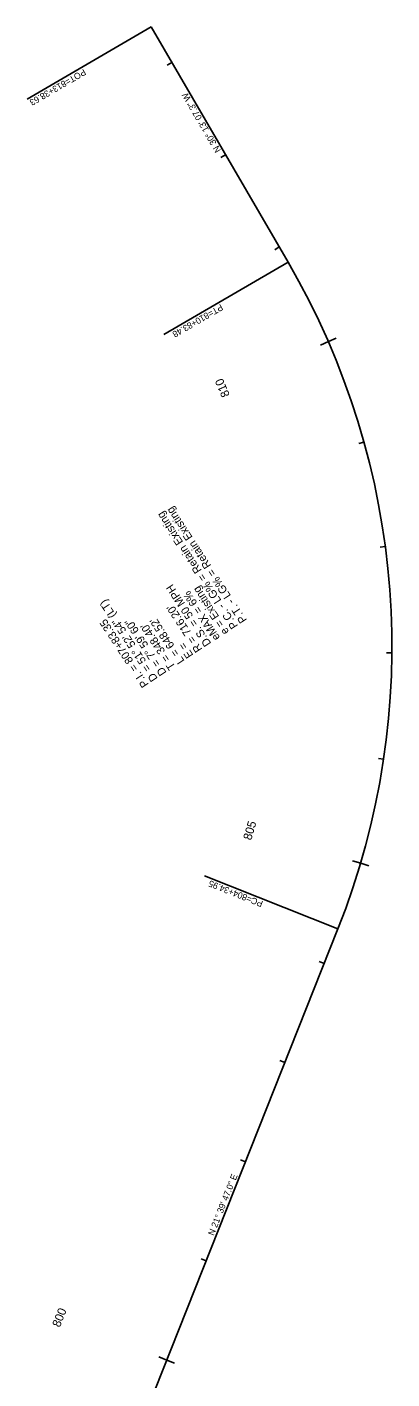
# Model space of a CAD drawing. Extents: x 1551641 to 1624343, y 1119533 to 1136600.
# Drawn here: x 1552292 to 1552634, y 1135333 to 1136600 of the extents above; entities that cross this region are included whole.
import ezdxf

# ---------------------------------------------------------------- set-up
doc = ezdxf.new("R2010")
doc.units = 0
for name, color, linetype in [('RD_HC_Cl', 7, 'Continuous'), ('RD_HC_Data', 7, 'Continuous'), ('RD_HC_Data_Tic', 7, 'Continuous'), ('RD_HC_TX_Sta50', 7, 'Continuous')]:
    doc.layers.add(name, color=color, linetype=linetype)

msp = doc.modelspace()

# ---------------------------------------------------------------- linework, layer by layer
at = {"layer": 'RD_HC_Cl'}
for p, q in [((1552536.7, 1136379.5), (1552408.3, 1136600)), ((1552389.3, 1135265.7), (1552583.4, 1135754.6))]:
    msp.add_line(p, q, dxfattribs=at)
msp.add_arc((1551917.8, 1136019), 716.2, 338.3369, 30.2187, dxfattribs=at)
at = {"layer": 'RD_HC_Data'}
for p, q in [((1552408.3, 1136600), (1552291.9, 1136532.2)), ((1552536.7, 1136379.5), (1552420.3, 1136311.7)), ((1552583.4, 1135754.6), (1552458.3, 1135804.4))]:
    msp.add_line(p, q, dxfattribs=at)
at = {"layer": 'RD_HC_Data_Tic'}
for p, q in [((1552427.7, 1136566.6), (1552423.4, 1136564.1)), ((1552478.1, 1136480.2), (1552473.7, 1136477.7)), ((1552528.4, 1136393.8), (1552524.1, 1136391.2)), ((1552574.4, 1136305.1), (1552567.1, 1136301.9)), ((1552581.8, 1136308.3), (1552574.4, 1136305.1)), ((1552607.8, 1136210.9), (1552603, 1136209.6)), ((1552627.8, 1136113), (1552622.9, 1136112.3)), ((1552634, 1136013.3), (1552629, 1136013.3)), ((1552626.2, 1135913.7), (1552621.3, 1135914.4)), ((1552604.7, 1135816.1), (1552597, 1135818.4)), ((1552612.4, 1135813.8), (1552604.7, 1135816.1)), ((1552570.5, 1135722.1), (1552565.9, 1135724)), ((1552533.6, 1135629.2), (1552529, 1135631.1)), ((1552496.7, 1135536.3), (1552492.1, 1135538.1)), ((1552459.8, 1135443.3), (1552455.1, 1135445.2)), ((1552422.9, 1135350.4), (1552415.4, 1135353.4)), ((1552430.3, 1135347.4), (1552422.9, 1135350.4))]:
    msp.add_line(p, q, dxfattribs=at)

# ---------------------------------------------------------------- texts
at = {"layer": 'RD_HC_Data'}
for s, height, rotation, p in [('POT=813+38.63', 6, 210.2187, (1552344.9, 1136561)), ('N 30%%d 13\' 07.3" W', 6, 120.2187, (1552473.9, 1136484.4)), ('PT=810+83.48', 6, 210.2187, (1552473.4, 1136340.5)), ('P.C. - LG% = Retain Existing', 7.5, 123.2337, (1552490, 1136038.7)), ('P.T. - LG% = Retain Existing', 7.5, 123.2337, (1552498.3, 1136044.1)), ('D.S. = 50 MPH', 7.5, 123.2337, (1552464.9, 1136022.2)), ('eMAX = 6%', 7.5, 123.2337, (1552473.2, 1136027.7)), ('e = Existing', 7.5, 123.2337, (1552481.6, 1136033.2)), ('    = 51%%d 52\' 54" (LT)', 7.5, 123.2337, (1552414.7, 1135989.3)), ("R = 716.20'", 7.5, 123.2337, (1552456.5, 1136016.7)), ('P.I. = 807+83.35', 7.5, 123.2337, (1552406.3, 1135983.8)), ('D = 7%%d 59\' 60"', 7.5, 123.2337, (1552423, 1135994.8)), ("L = 648.52'", 7.5, 123.2337, (1552439.8, 1136005.8)), ("T = 348.40'", 7.5, 123.2337, (1552431.4, 1136000.3)), ('E =', 7.5, 123.2337, (1552448.1, 1136011.2)), ('D', 7.5, 123.2337, (1552414.7, 1135989.3)), ('PC=804+34.95', 6, 158.3369, (1552513.7, 1135780.4)), ('N 21%%d 39\' 47.0" E', 6, 68.3369, (1552466.9, 1135466.6))]:
    msp.add_text(s, height=height, rotation=rotation, dxfattribs=at).set_placement(p)
at = {"layer": 'RD_HC_TX_Sta50'}
for s, rotation, p in [('810', 113.5147, (1552482.2, 1136255)), ('805', 73.5322, (1552502, 1135837.2)), ('800', 68.3369, (1552322.6, 1135380.6))]:
    msp.add_text(s, height=8, rotation=rotation, dxfattribs=at).set_placement(p)

doc.saveas('drawing.dxf')
